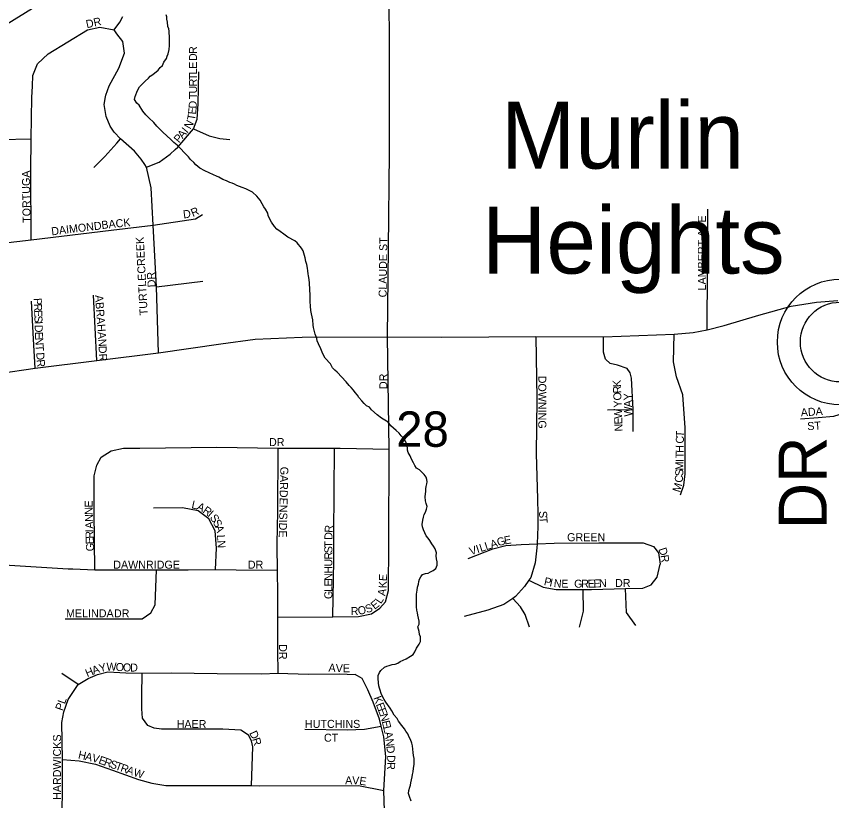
# Model space of a CAD drawing. Extents: x 8.5 to 81.5, y -1.2 to 22.4.
# Drawn here: x 51.227 to 52.191, y 16.85 to 17.778 of the extents above; entities that cross this region are included whole.
import ezdxf

# ---------------------------------------------------------------- set-up
doc = ezdxf.new("R2010")
doc.units = 0
for name, color, linetype in [('GM_X_County_Road', 7, 'Continuous'), ('GM_X_County_Road_Text', 7, 'Continuous'), ('GM_X_Interchange_Ramps', 7, 'Continuous'), ('GM_X_Minor_River', 7, 'Continuous'), ('GM_X_Section_Text', 7, 'Continuous'), ('GM_X_Township_Subdivision', 7, 'Continuous'), ('GM_X_Township_Subdivision_Text', 7, 'Continuous'), ('GM_X_Unincorporated', 7, 'Continuous'), ('GM_X_Unincorporated_Text', 7, 'Continuous')]:
    doc.layers.add(name, color=color, linetype=linetype)

msp = doc.modelspace()

# ---------------------------------------------------------------- linework, layer by layer
at = {"layer": 'GM_X_County_Road'}
for points in [[(51.66589, 17.39907), (51.73007, 17.39853), (51.84117, 17.39935), (51.921, 17.39907), (52.00487, 17.40204), (52.02725, 17.40393), (52.0437, 17.40744), (52.06366, 17.41229), (52.10492, 17.42469), (52.1432, 17.43521), (52.17314, 17.44007), (52.19804, 17.4418)], [(50.74119, 17.32303), (50.77004, 17.32626), (50.79566, 17.32545), (50.8318, 17.32222), (50.86712, 17.3206), (50.90056, 17.3206), (50.92349, 17.32087), (50.95504, 17.32276), (51.0176, 17.32869), (51.09068, 17.33921), (51.15269, 17.34812), (51.16968, 17.35082), (51.20583, 17.35566), (51.2492, 17.36202), (51.32215, 17.37089), (51.39511, 17.38016), (51.46849, 17.39072), (51.50921, 17.39611), (51.56496, 17.39869), (51.66589, 17.39907)]]:
    msp.add_lwpolyline(points, dxfattribs=at)
at = {"layer": 'GM_X_Interchange_Ramps'}
msp.add_lwpolyline([(51.20211, 17.76076), (51.25954, 17.79597), (51.27714, 17.80636), (51.29042, 17.81443), (51.3034, 17.82165), (51.32014, 17.82915), (51.33457, 17.83493), (51.3464, 17.83839), (51.35766, 17.84127), (51.36978, 17.84416), (51.39122, 17.84751), (51.41161, 17.84948), (51.4583, 17.85047), (51.52275, 17.85179), (51.52242, 17.86362)], dxfattribs=at)
at = {"layer": 'GM_X_Minor_River'}
for points in [[(51.5693, 17.48817), (51.56825, 17.49237), (51.56754, 17.49505), (51.56614, 17.50078), (51.56393, 17.50386), (51.55874, 17.51005), (51.55613, 17.51238), (51.54788, 17.51672), (51.54302, 17.52024), (51.53891, 17.52336), (51.53479, 17.52611), (51.5322, 17.52958), (51.52851, 17.5346), (51.52668, 17.53805), (51.52449, 17.54228), (51.52418, 17.54532), (51.52162, 17.54993), (51.5194, 17.55264), (51.51757, 17.5561), (51.51501, 17.56071), (51.51131, 17.56534), (51.50609, 17.57001), (51.50234, 17.57198), (51.4982, 17.57397), (51.49406, 17.57557), (51.49067, 17.57678), (51.48766, 17.57798), (51.48466, 17.57956), (51.48203, 17.58075), (51.47939, 17.58156), (51.47526, 17.58354), (51.47112, 17.58515), (51.46624, 17.5879), (51.46361, 17.5891), (51.45984, 17.59069), (51.45496, 17.59307), (51.4497, 17.59546), (51.44369, 17.59862), (51.43922, 17.60251), (51.43662, 17.60522), (51.43289, 17.60871), (51.4303, 17.61181), (51.42472, 17.61724), (51.42176, 17.62072), (51.41693, 17.62575), (51.4132, 17.62887), (51.40985, 17.63198), (51.40426, 17.63703), (51.40054, 17.64052), (51.3931, 17.64827), (51.3894, 17.65253), (51.38344, 17.65797), (51.3801, 17.66145), (51.37639, 17.66571), (51.37199, 17.67302), (51.36938, 17.67535), (51.36643, 17.67959), (51.36727, 17.68337), (51.37006, 17.69016), (51.37243, 17.69467), (51.3763, 17.69839), (51.37902, 17.70138), (51.38326, 17.70472), (51.38521, 17.70734), (51.38828, 17.70918), (51.39446, 17.71437), (51.3968, 17.71737), (51.39951, 17.71997), (51.4011, 17.72374), (51.40423, 17.72824), (51.40505, 17.73088), (51.40624, 17.73352), (51.40749, 17.73882), (51.40796, 17.74337), (51.40814, 17.75211), (51.40755, 17.76048), (51.40723, 17.76315), (51.40614, 17.76583), (51.40549, 17.77116), (51.40481, 17.7746), (51.40486, 17.77726), (51.40416, 17.77993)], [(51.7014, 17.1028), (51.70224, 17.10658), (51.70268, 17.10961), (51.70349, 17.11226), (51.70507, 17.11527), (51.70703, 17.11789), (51.71084, 17.11895), (51.71389, 17.11965), (51.71658, 17.12112), (51.71964, 17.12258), (51.72273, 17.12517), (51.72433, 17.12894), (51.72441, 17.13274), (51.72372, 17.13656), (51.72342, 17.13998), (51.72349, 17.1434), (51.72207, 17.14837), (51.72024, 17.15145), (51.71801, 17.15415), (51.71582, 17.158), (51.71398, 17.1607), (51.71138, 17.16379), (51.70811, 17.1707), (51.70704, 17.17414), (51.70672, 17.17718), (51.70759, 17.18211), (51.70842, 17.18589), (51.70924, 17.18892), (51.71081, 17.19155), (51.71203, 17.19532), (51.71247, 17.19835), (51.7114, 17.2018), (51.71071, 17.20485), (51.71043, 17.2098), (51.71094, 17.21625), (51.711, 17.21929), (51.71144, 17.22194), (51.71226, 17.22496), (51.71269, 17.22762), (51.71237, 17.23028), (51.71128, 17.23296), (51.70907, 17.23605), (51.7061, 17.23915), (51.70349, 17.24148), (51.70013, 17.24383), (51.69791, 17.24692), (51.69646, 17.24999), (51.69427, 17.25421), (51.69245, 17.25805), (51.69026, 17.26227), (51.68955, 17.26495), (51.68923, 17.26761), (51.68854, 17.27105), (51.68748, 17.27487), (51.68527, 17.27796), (51.68193, 17.28182), (51.67972, 17.28491), (51.67599, 17.28802), (51.66966, 17.29385), (51.66633, 17.2981), (51.65846, 17.30282), (51.6536, 17.30671), (51.64689, 17.31255), (51.6443, 17.31564), (51.64092, 17.31723), (51.63832, 17.31994), (51.63535, 17.32342), (51.63202, 17.32729), (51.63018, 17.32999), (51.62758, 17.33308), (51.62536, 17.33579), (51.62277, 17.33888), (51.62055, 17.34158), (51.61684, 17.34584), (51.60607, 17.35707), (51.60346, 17.35941), (51.60086, 17.36212), (51.59831, 17.36711), (51.59199, 17.3737), (51.58944, 17.37869), (51.58691, 17.38482), (51.58399, 17.39058), (51.58255, 17.39441), (51.58223, 17.39708), (51.58005, 17.40206), (51.57832, 17.41008), (51.57799, 17.41275), (51.57737, 17.41922), (51.57599, 17.42609), (51.57494, 17.43029), (51.57466, 17.43524), (51.5744, 17.44094), (51.57416, 17.44779), (51.5737, 17.46224), (51.57303, 17.46681), (51.57236, 17.47101), (51.57204, 17.47367), (51.57135, 17.47711), (51.57103, 17.48016), (51.57036, 17.48435), (51.5693, 17.48817)], [(51.69355, 16.84981), (51.69177, 16.85517), (51.6907, 16.85899), (51.69115, 16.86241), (51.69199, 16.86619), (51.6928, 16.86883), (51.69324, 16.87149), (51.69407, 16.87489), (51.6949, 16.87868), (51.69534, 16.88133), (51.69616, 16.88435), (51.69663, 16.8889), (51.6971, 16.89308), (51.69715, 16.89573), (51.69724, 16.90029), (51.69656, 16.90373), (51.69625, 16.90754), (51.69557, 16.91135), (51.69527, 16.91516), (51.69459, 16.91859), (51.69278, 16.92281), (51.69131, 16.9255), (51.68987, 16.92933), (51.68728, 16.93242), (51.68582, 16.93549), (51.68249, 16.93936), (51.6788, 16.94437), (51.67734, 16.94745), (51.67363, 16.9517), (51.6707, 16.9567), (51.66887, 16.95978), (51.6637, 16.96672), (51.66187, 16.97018), (51.65931, 16.97441), (51.65822, 16.9771), (51.65716, 16.98092), (51.65608, 16.9836), (51.65537, 16.98627), (51.65506, 16.9897), (51.6548, 16.99503), (51.65487, 16.99845), (51.65645, 17.00184), (51.65802, 17.00447), (51.66228, 17.00818), (51.66496, 17.00965), (51.66763, 17.01035), (51.67107, 17.01142), (51.67487, 17.01173), (51.67793, 17.01319), (51.68063, 17.01503), (51.68791, 17.01831), (51.6929, 17.02125), (51.69597, 17.02309), (51.69794, 17.02647), (51.69992, 17.03061), (51.70306, 17.03549), (51.70464, 17.0385), (51.70469, 17.04116), (51.70475, 17.0442), (51.70367, 17.04688), (51.70336, 17.05031), (51.70228, 17.05337), (51.70158, 17.05604), (51.70316, 17.05905), (51.70324, 17.06285), (51.70255, 17.06629), (51.70148, 17.06973), (51.70116, 17.07239), (51.70047, 17.07583), (51.70017, 17.07964), (51.70022, 17.08229), (51.69993, 17.08648), (51.70001, 17.09028), (51.70009, 17.09446), (51.70095, 17.09938), (51.7014, 17.1028)]]:
    msp.add_lwpolyline(points, dxfattribs=at)
at = {"layer": 'GM_X_Township_Subdivision'}
for points in [[(51.66589, 17.39907), (51.66677, 17.50389), (51.66823, 17.61639), (51.66822, 17.75998), (51.66674, 17.83398)], [(51.3427, 17.76212), (51.34921, 17.77103), (51.35279, 17.77789)], [(51.24588, 17.69561), (51.24655, 17.70812), (51.25182, 17.72179), (51.2646, 17.73369), (51.31084, 17.76212), (51.32557, 17.7652), (51.3427, 17.76212)], [(51.33245, 17.68277), (51.33281, 17.68462), (51.33667, 17.69585), (51.34824, 17.71688), (51.3549, 17.73441), (51.35279, 17.74808), (51.34578, 17.7572), (51.3427, 17.76212)], [(51.41479, 17.62052), (51.41766, 17.62327), (51.43623, 17.64501), (51.44057, 17.65648), (51.44195, 17.67468), (51.44255, 17.71232)], [(51.24457, 17.51372), (51.24418, 17.59556), (51.24457, 17.633), (51.24516, 17.68217), (51.24588, 17.69561)], [(51.37885, 17.60277), (51.37453, 17.60925), (51.36647, 17.61836), (51.34999, 17.63309), (51.34262, 17.64115), (51.33772, 17.64816), (51.33315, 17.65973), (51.3307, 17.67376), (51.33245, 17.68277)], [(51.43623, 17.64501), (51.45482, 17.63659), (51.46744, 17.63344), (51.47936, 17.63239)], [(51.20562, 17.63185), (51.20789, 17.63223), (51.24457, 17.633)], [(51.31843, 17.59907), (51.3314, 17.6124), (51.34578, 17.62782), (51.34999, 17.63309)], [(51.38084, 17.59978), (51.39557, 17.60539), (51.40889, 17.61486), (51.41479, 17.62052)], [(51.39511, 17.38016), (51.39279, 17.45813), (51.38855, 17.53109), (51.3861, 17.57524), (51.38084, 17.59978), (51.37885, 17.60277)], [(52.0437, 17.40744), (52.04433, 17.54976)], [(51.17161, 17.50793), (51.19998, 17.50851), (51.24457, 17.51372), (51.33914, 17.5253), (51.38855, 17.53109), (51.43873, 17.53843), (51.44687, 17.54374)], [(51.39279, 17.45813), (51.44722, 17.4647)], [(51.32215, 17.37089), (51.31791, 17.4481)], [(51.2492, 17.36202), (51.24727, 17.39637), (51.24495, 17.44115)], [(51.66718, 17.1551), (51.66787, 17.26622), (51.66589, 17.39907)], [(51.84117, 17.39935), (51.84235, 17.32584), (51.8417, 17.26065), (51.84303, 17.20742), (51.8434, 17.18915)], [(51.95633, 17.28716), (51.95633, 17.31305), (51.95444, 17.35), (51.95282, 17.3562), (51.94904, 17.36159), (51.93772, 17.36536), (51.92909, 17.36725), (51.92369, 17.37238), (51.92127, 17.38101), (51.921, 17.39907)], [(52.01214, 17.21219), (52.01619, 17.22352), (52.01754, 17.237), (52.01781, 17.29121), (52.01511, 17.33031), (52.00729, 17.35161), (52.00405, 17.36941), (52.00487, 17.40204)], [(51.92585, 17.31251), (51.95633, 17.31305)], [(52.15403, 17.30204), (52.17496, 17.3035), (52.19343, 17.30527), (52.20734, 17.30932)], [(51.31986, 17.12323), (51.31886, 17.19221), (51.31885, 17.23449), (51.32203, 17.24719), (51.32731, 17.2567), (51.33894, 17.2641), (51.35375, 17.26728), (51.37279, 17.26728), (51.46375, 17.26835), (51.53619, 17.26739), (51.54413, 17.26729), (51.60288, 17.26729), (51.60971, 17.26729), (51.66787, 17.26622)], [(51.53619, 17.26739), (51.53568, 17.19221), (51.53481, 17.1547)], [(51.60238, 17.14133), (51.60231, 17.16472), (51.60288, 17.26729)], [(51.46226, 17.12392), (51.46353, 17.1491), (51.46205, 17.16941), (51.45443, 17.18358), (51.44174, 17.19331), (51.42333, 17.1967), (51.38907, 17.19628)], [(51.8434, 17.18915), (51.84341, 17.18865), (51.84369, 17.17482), (51.84261, 17.15418), (51.84237, 17.14954), (51.84036, 17.1316), (51.83504, 17.11429), (51.83302, 17.11135), (51.82773, 17.10365), (51.81709, 17.09169), (51.81384, 17.08952), (51.80311, 17.08237), (51.78448, 17.07571), (51.75654, 17.06841)], [(51.53481, 17.1547), (51.53473, 17.15097), (51.53524, 17.12287), (51.53567, 17.09473), (51.53567, 17.06744), (51.53567, 17.03175)], [(51.53567, 17.06744), (51.60104, 17.06786), (51.63129, 17.06808), (51.64695, 17.07146), (51.65668, 17.07823), (51.66323, 17.08562), (51.66682, 17.09916), (51.66718, 17.1551)], [(51.76118, 17.13692), (51.79045, 17.14823), (51.80576, 17.15222), (51.82373, 17.15355), (51.84261, 17.15418), (51.86299, 17.15486), (51.91557, 17.15552), (51.96812, 17.15552), (51.98011, 17.15085), (51.9861, 17.14354), (51.98809, 17.13023)], [(51.60104, 17.06786), (51.60239, 17.1347), (51.60238, 17.14133)], [(51.20576, 17.12959), (51.28803, 17.12462)], [(51.28441, 17.06529), (51.37563, 17.06557), (51.38585, 17.07248), (51.3911, 17.08188), (51.39245, 17.1235)], [(51.28803, 17.12462), (51.28837, 17.1246), (51.29349, 17.12453), (51.31986, 17.12323), (51.34929, 17.1235), (51.36011, 17.1235)], [(51.36011, 17.1235), (51.39245, 17.1235), (51.43011, 17.12329), (51.46226, 17.12392), (51.4868, 17.12329), (51.53524, 17.12287)], [(51.83302, 17.11135), (51.84968, 17.10298), (51.86499, 17.10031), (51.897, 17.10031), (51.90692, 17.10031), (51.94696, 17.10119), (51.96746, 17.10165), (51.97744, 17.10562), (51.98477, 17.11493), (51.98809, 17.13023)], [(51.89294, 17.05574), (51.8976, 17.07437), (51.897, 17.10031)], [(51.95947, 17.05774), (51.94817, 17.07304), (51.94696, 17.10119)], [(51.83372, 17.05575), (51.8284, 17.07039), (51.82307, 17.0797), (51.81384, 17.08952)], [(51.53567, 17.03175), (51.53567, 17.02809), (51.53588, 17.00102)], [(51.29989, 16.98776), (51.2808, 17.00081)], [(51.29989, 16.98776), (51.31177, 16.99508), (51.32297, 16.99964), (51.33513, 17.00268), (51.35638, 17.00155), (51.37553, 17.00112), (51.41011, 17.00165), (51.46448, 17.00081), (51.51684, 17.00059), (51.53588, 17.00102), (51.57184, 17.00017), (51.60844, 17.00059), (51.62749, 16.99953)], [(51.50499, 16.86837), (51.50637, 16.91418), (51.50499, 16.92115), (51.5014, 16.92793), (51.49219, 16.93395), (51.47093, 16.9349), (51.4227, 16.9348), (51.39848, 16.93501), (51.3897, 16.93628), (51.38234, 16.9395), (51.376, 16.94795), (51.37521, 16.95891), (51.3751, 16.97478), (51.37553, 17.00112)], [(51.64631, 16.80755), (51.65371, 16.81506), (51.66038, 16.82744), (51.66218, 16.83833), (51.66157, 16.86231), (51.66368, 16.90249), (51.66156, 16.92574), (51.65835, 16.93858), (51.65627, 16.94689), (51.64887, 16.96698), (51.6425, 16.98134), (51.63573, 16.99509), (51.62749, 16.99953)], [(51.28033, 16.8085), (51.28096, 16.83146), (51.28128, 16.86932), (51.28149, 16.89915), (51.28081, 16.94267), (51.28291, 16.95536), (51.28822, 16.97016), (51.29989, 16.98776)], [(51.56804, 16.93501), (51.61817, 16.93438), (51.6387, 16.9348), (51.65835, 16.93858)], [(51.28149, 16.89915), (51.30127, 16.89767), (51.32042, 16.89376), (51.34041, 16.88667), (51.3714, 16.87535), (51.38705, 16.87101), (51.40356, 16.86848), (51.50499, 16.86837), (51.51483, 16.86795), (51.63129, 16.86816), (51.66157, 16.86231)]]:
    msp.add_lwpolyline(points, dxfattribs=at)
at = {"layer": 'GM_X_Unincorporated'}
for radius in [0.0744, 0.04716]:
    msp.add_circle((52.20114, 17.39284), radius, dxfattribs=at)

# ---------------------------------------------------------------- texts
at = {"layer": 'GM_X_County_Road_Text'}
msp.add_text('DR', height=0.056818, rotation=90, dxfattribs=at).set_placement((52.18515, 17.17134))
at = {"layer": 'GM_X_Section_Text'}
msp.add_text('28', height=0.041856, rotation=0.00001, dxfattribs=at).set_placement((51.67604, 17.2689))
at = {"layer": 'GM_X_Township_Subdivision_Text'}
for s, height, rotation, p in [('DR', 0.00947, 12.52366, (51.31024, 17.76391)), ('R', 0.00947, 89.99405, (51.4405, 17.73346)), ('D', 0.00947, 89.99284, (51.4405, 17.72513)), ('E', 0.00947, 89.99561, (51.4405, 17.71597)), ('L', 0.00947, 89.99561, (51.4405, 17.7093)), ('T', 0.00947, 89.99561, (51.4405, 17.70263)), ('R', 0.00947, 89.99405, (51.4405, 17.69513)), ('U', 0.00947, 89.99284, (51.4405, 17.6868)), ('T', 0.00947, 89.85738, (51.44049, 17.68011)), ('D', 0.00947, 86.52484, (51.43994, 17.6687)), ('T', 0.00947, 80.12128, (51.43796, 17.65435)), ('E', 0.00947, 84.02081, (51.4392, 17.66161)), ('N', 0.00947, 60.62536, (51.4327, 17.64379)), ('I', 0.00947, 50.02079, (51.42893, 17.63902)), ('P', 0.00947, 50.02999, (51.41929, 17.62753)), ('A', 0.00947, 50.01323, (51.42357, 17.63263)), ('TORTUGA', 0.00947, 90.87087, (51.24384, 17.53381)), ('D', 0.00947, 7.27685, (51.4246, 17.53894)), ('R', 0.00947, 23.02091, (51.43556, 17.54072)), ('BACK', 0.00947, 5.85317, (51.32794, 17.52644)), ('LAMBERT AVE', 0.0094697, 90, (52.04217, 17.45383)), ('DAIMOND', 0.00947, 6.91093, (51.26874, 17.51894)), ('TURTLECREEK', 0.0094697, 92.8917, (51.38217, 17.4247)), ('CLAUDE ST', 0.00947, 89.24656, (51.66467, 17.44553)), ('DR', 0.00947, 92.86078, (51.39161, 17.45776)), ('P', 0.00947, 271.99471, (51.2474, 17.44473)), ('ABRAHAN', 0.00947, 274.20644, (51.31986, 17.44813)), ('R', 0.00947, 271.96742, (51.24763, 17.43807)), ('E', 0.00947, 272.00219, (51.24789, 17.43057)), ('S', 0.00947, 271.99471, (51.24812, 17.4239)), ('I', 0.00947, 271.96742, (51.24836, 17.41724)), ('D', 0.00947, 271.99879, (51.2485, 17.41307)), ('E', 0.00947, 272.2153, (51.24879, 17.40471)), ('N', 0.00947, 273.67033, (51.24906, 17.39778)), ('T', 0.00947, 274.26853, (51.2496, 17.38935)), ('DR', 0.00947, 273.01099, (51.32403, 17.38809)), ('D', 0.00947, 274.26958, (51.25028, 17.38021)), ('R', 0.00947, 274.29347, (51.2509, 17.3719)), ('DR', 0.00947, 90, (51.66551, 17.33717)), ('DOWNING', 0.00947, 270, (51.84407, 17.353)), ('K', 0.00947, 92.18581, (51.94183, 17.33968)), ('R', 0.00947, 92.18581, (51.94211, 17.33219)), ('O', 0.00947, 92.20248, (51.94244, 17.32386)), ('Y', 0.00947, 92.29232, (51.95466, 17.32412)), ('Y', 0.00947, 92.18581, (51.94275, 17.31553)), ('A', 0.00947, 92.02125, (51.95495, 17.31574)), ('W', 0.00947, 90.89124, (51.95513, 17.30471)), ('W', 0.00947, 92.18645, (51.94326, 17.30221)), ('ADA', 0.00947, 3.81939, (52.15467, 17.30478)), ('E', 0.00947, 92.20227, (51.94352, 17.29555)), ('ST', 0.00947, 3.57463, (52.16236, 17.28852)), ('N', 0.00947, 92.18581, (51.94384, 17.28721)), ('T', 0.00947, 89.04378, (52.01621, 17.28014)), ('DR', 0.00947, 0.00001, (51.52562, 17.26978)), ('C', 0.00947, 89.07712, (52.01609, 17.27264)), ('H', 0.00947, 89.03823, (52.0159, 17.2618)), ('T', 0.00947, 89.07774, (52.0158, 17.25513)), ('M', 0.00947, 88.90984, (52.01554, 17.24094)), ('I', 0.00947, 89.05803, (52.01573, 17.25096)), ('GARDENSIDE', 0.00947, 268.71333, (51.53907, 17.24546)), ('S', 0.00947, 87.84476, (52.01528, 17.23408)), ('C', 0.00947, 85.48534, (52.01466, 17.22618)), ('M', 0.00947, 73.60429, (52.01145, 17.21448)), ('E', 0.00947, 90.05466, (51.31718, 17.197)), ('L', 0.00947, 347.07706, (51.4334, 17.19643)), ('A', 0.00947, 333.70867, (51.43935, 17.19514)), ('N', 0.00947, 90.85249, (51.3173, 17.1887)), ('R', 0.00947, 325.21885, (51.4465, 17.19163)), ('I', 0.00947, 318.71129, (51.45244, 17.18753)), ('S', 0.00947, 272.26878, (51.8449, 17.1929)), ('N', 0.00947, 92.03294, (51.3176, 17.18042)), ('S', 0.00947, 304.44801, (51.45516, 17.18525)), ('S', 0.00947, 297.6771, (51.45878, 17.18)), ('T', 0.00947, 274.45622, (51.84519, 17.18585)), ('A', 0.00947, 92.03294, (51.31789, 17.17209)), ('A', 0.00947, 287.33578, (51.4617, 17.17452)), ('R', 0.00947, 86.257, (51.60071, 17.16701)), ('I', 0.00947, 92.05478, (51.31804, 17.16793)), ('R', 0.00947, 92.04798, (51.31831, 17.16043)), ('L', 0.00947, 272.59637, (51.46422, 17.1647)), ('D', 0.00947, 88.66676, (51.60052, 17.15878)), ('G', 0.00947, 16.85206, (51.79668, 17.15108)), ('E', 0.00947, 9.08056, (51.80432, 17.15342)), ('GREEN', 0.00947, 0.00001, (51.87812, 17.15728)), ('E', 0.00947, 92.02202, (51.31854, 17.15377)), ('G', 0.00947, 92.03294, (51.31884, 17.14544)), ('N', 0.00947, 272.09846, (51.46452, 17.15806)), ('T', 0.00947, 89.97267, (51.60051, 17.14967)), ('V', 0.00947, 18.02027, (51.76423, 17.14053)), ('I', 0.00947, 17.99273, (51.77216, 17.1431)), ('L', 0.00947, 18.02072, (51.77612, 17.14439)), ('L', 0.00947, 18.02072, (51.78246, 17.14646)), ('A', 0.00947, 18.02027, (51.7888, 17.14852)), ('S', 0.00947, 89.99561, (51.60051, 17.143)), ('R', 0.00947, 89.9757, (51.60051, 17.1355)), ('D', 0.00947, 288.5248, (51.98597, 17.14792)), ('DAWNRIDGE', 0.00947, 0.00001, (51.34145, 17.12478)), ('DR', 0.00947, 0.00001, (51.50062, 17.12478)), ('U', 0.00947, 89.99284, (51.60051, 17.12717)), ('R', 0.00947, 278.30866, (51.98852, 17.14045)), ('H', 0.00947, 89.97813, (51.60051, 17.11883)), ('N', 0.00947, 89.97813, (51.6005, 17.1105)), ('E', 0.00947, 88.18476, (51.66504, 17.10999)), ('P', 0.00947, 347.72014, (51.85018, 17.10557)), ('E', 0.00947, 90, (51.6005, 17.10384)), ('K', 0.00947, 87.33571, (51.66464, 17.10151)), ('I', 0.00947, 347.72172, (51.8567, 17.10415)), ('N', 0.00947, 354.79104, (51.86201, 17.10308)), ('E', 0.00947, 359.99425, (51.87123, 17.10228)), ('G', 0.00947, 0.02186, (51.88645, 17.10228)), ('R', 0.00947, 0.04154, (51.89479, 17.10229)), ('E', 0.00947, 0.94972, (51.90245, 17.1023)), ('E', 0.00947, 2.34035, (51.90937, 17.10241)), ('N', 0.00947, 2.60832, (51.91608, 17.10269)), ('DR', 0.00947, 0.00001, (51.93479, 17.10311)), ('G', 0.00947, 89.97813, (51.6005, 17.08883)), ('L', 0.00947, 89.99561, (51.6005, 17.09717)), ('A', 0.00947, 80.1366, (51.66307, 17.09201)), ('E', 0.00947, 39.1352, (51.65061, 17.07596)), ('L', 0.00947, 57.03814, (51.65793, 17.08256)), ('MELINDA', 0.00947, 0.00001, (51.28562, 17.06725)), ('DR', 0.00947, 0.00001, (51.34229, 17.06725)), ('R', 0.00947, 1.4327, (51.62235, 17.06979)), ('O', 0.00947, 10.07421, (51.6314, 17.07013)), ('S', 0.00947, 19.36251, (51.64123, 17.07201)), ('DR', 0.00947, 270, (51.5374, 17.0355)), ('H', 0.00947, 22.56439, (51.31073, 16.9963)), ('A', 0.00947, 20.08021, (51.31832, 16.99945)), ('Y', 0.00947, 13.7023, (51.32588, 17.00223)), ('W', 0.00947, 359.66376, (51.33337, 17.00414)), ('O', 0.00947, 355.69014, (51.34403, 17.00408)), ('O', 0.00947, 357.94361, (51.35275, 17.00343)), ('D', 0.00947, 359.92533, (51.36143, 17.00313)), ('A', 0.00947, 356.30369, (51.59574, 17.00311)), ('V', 0.00947, 358.1913, (51.6044, 17.00256)), ('E', 0.00947, 359.90728, (51.61304, 17.00229)), ('PL', 0.00947, 70.56063, (51.28144, 16.95609)), ('K', 0.00947, 290.6891, (51.64889, 16.97203)), ('E', 0.00947, 290.69035, (51.65184, 16.96423)), ('E', 0.00947, 290.69035, (51.65419, 16.958)), ('N', 0.00947, 287.23931, (51.6565, 16.9519)), ('HAER', 0.00947, 0.00001, (51.41645, 16.93633)), ('HUTCHINS', 0.00947, 0.00001, (51.56812, 16.93646)), ('E', 0.00947, 283.20142, (51.65892, 16.94411)), ('D', 0.00947, 294.95221, (51.50208, 16.93048)), ('L', 0.00947, 282.86359, (51.66044, 16.93764)), ('A', 0.00947, 280.52969, (51.66191, 16.93123)), ('HARDWICKS', 0.00947, 90, (51.27967, 16.85134)), ('R', 0.00947, 287.76688, (51.50548, 16.92321)), ('CT', 0.00947, 0.00001, (51.59062, 16.92016)), ('N', 0.00947, 276.43916, (51.6634, 16.92322)), ('D', 0.00947, 275.93464, (51.66433, 16.91496)), ('H', 0.00947, 346.92346, (51.29935, 16.90057)), ('A', 0.00947, 346.92346, (51.30747, 16.89869)), ('V', 0.00947, 344.67012, (51.31549, 16.89683)), ('E', 0.00947, 340.70093, (51.32336, 16.89468)), ('D', 0.00947, 270.28419, (51.66538, 16.90443)), ('R', 0.00947, 340.2057, (51.32963, 16.89248)), ('S', 0.00947, 340.20832, (51.33669, 16.88994)), ('T', 0.00947, 340.20832, (51.34296, 16.88768)), ('R', 0.00947, 340.2057, (51.34923, 16.88543)), ('R', 0.00947, 267.64337, (51.66543, 16.89621)), ('A', 0.00947, 340.19619, (51.35629, 16.88289)), ('W', 0.00947, 342.5944, (51.36453, 16.87992)), ('A', 0.00947, 359.82512, (51.61561, 16.86978)), ('V', 0.00947, 358.0326, (51.62386, 16.86976)), ('E', 0.00947, 351.55301, (51.63191, 16.8695))]:
    msp.add_text(s, height=height, rotation=rotation, dxfattribs=at).set_placement(p)
at = {"layer": 'GM_X_Unincorporated_Text'}
for s, p in [('Murlin', (51.79979, 17.59796)), ('Heights', (51.77729, 17.47379))]:
    msp.add_text(s, height=0.078977, rotation=0.00001, dxfattribs=at).set_placement(p)

doc.saveas('drawing.dxf')
